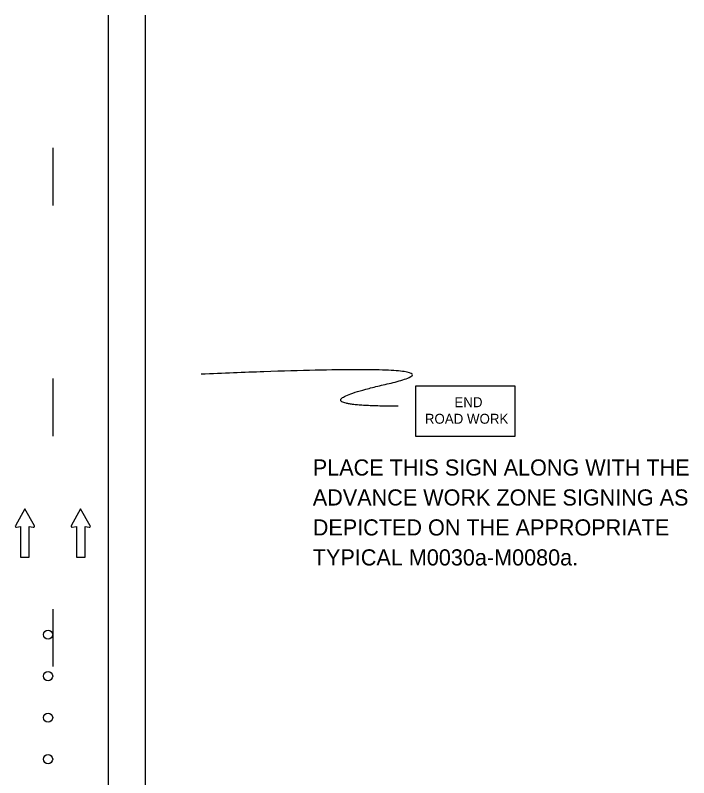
# Model space of a CAD drawing. Extents: x 16735 to 18475, y 6983 to 8262.
# Drawn here: x 17072.8 to 17364.7, y 7864.5 to 8195.2 of the extents above; entities that cross this region are included whole.
import ezdxf

# ---------------------------------------------------------------- set-up
doc = ezdxf.new("R2010")
doc.units = 0
for name, color, linetype in [('ALI_LEGAL_EX', 7, 'Continuous'), ('MT_SCRATCH_LEVEL_E', 7, 'Continuous'), ('PAVT_EDGE_EX', 7, 'Continuous'), ('TRAFFIC_SIGNS_PR', 7, 'Continuous')]:
    doc.layers.add(name, color=color, linetype=linetype)

msp = doc.modelspace()

# ---------------------------------------------------------------- linework, layer by layer
at = {"layer": 'ALI_LEGAL_EX'}
for points in [[(17089.08, 8137.7), (17089.08, 8112.7)], [(17089.08, 8037.7), (17089.08, 8012.7)], [(17089.08, 7937.7), (17089.08, 7912.7)]]:
    msp.add_lwpolyline(points, dxfattribs=at)
at = {"layer": 'MT_SCRATCH_LEVEL_E'}
for p, q in [((17077.02, 7981.08), (17072.9, 7973.84)), ((17077.02, 7981.08), (17072.9, 7973.84)), ((17081.16, 7973.84), (17077.02, 7981.08)), ((17081.16, 7973.84), (17077.02, 7981.08)), ((17101.19, 7981.08), (17097.08, 7973.84)), ((17101.19, 7981.08), (17097.08, 7973.84)), ((17105.33, 7973.84), (17101.19, 7981.08)), ((17105.33, 7973.84), (17101.19, 7981.08)), ((17073.39, 7973.15), (17075.16, 7973.47)), ((17073.39, 7973.15), (17075.16, 7973.47)), ((17075.16, 7973.47), (17075.16, 7960.21)), ((17075.16, 7973.47), (17075.16, 7960.21)), ((17078.91, 7960.21), (17078.91, 7973.47)), ((17078.91, 7973.47), (17080.68, 7973.15)), ((17078.91, 7960.21), (17078.91, 7973.47)), ((17078.91, 7973.47), (17080.68, 7973.15)), ((17097.56, 7973.15), (17099.33, 7973.47)), ((17097.56, 7973.15), (17099.33, 7973.47)), ((17099.33, 7973.47), (17099.33, 7960.21)), ((17099.33, 7973.47), (17099.33, 7960.21)), ((17103.08, 7960.21), (17103.08, 7973.47)), ((17103.08, 7973.47), (17104.85, 7973.15)), ((17103.08, 7960.21), (17103.08, 7973.47)), ((17103.08, 7973.47), (17104.85, 7973.15)), ((17075.16, 7960.21), (17078.91, 7960.21)), ((17075.16, 7960.21), (17078.91, 7960.21)), ((17099.33, 7960.21), (17103.08, 7960.21)), ((17099.33, 7960.21), (17103.08, 7960.21))]:
    msp.add_line(p, q, dxfattribs=at)
for centre, start, end in [((17073.31, 7973.61), 150.4248, 279.9638), ((17073.31, 7973.61), 150.4248, 279.9638), ((17080.75, 7973.61), 260.0362, 29.7731), ((17080.75, 7973.61), 260.0362, 29.7731), ((17097.48, 7973.61), 150.4248, 279.9638), ((17097.48, 7973.61), 150.4248, 279.9638), ((17104.92, 7973.61), 260.0362, 29.7731), ((17104.92, 7973.61), 260.0362, 29.7731)]:
    msp.add_arc(centre, 0.463, start, end, dxfattribs=at)
at = {"layer": 'PAVT_EDGE_EX'}
for p, q in [((17113.08, 8195.21), (17113.08, 7357.91)), ((17129.08, 8195.21), (17129.08, 7357.91))]:
    msp.add_line(p, q, dxfattribs=at)
at = {"layer": 'TRAFFIC_SIGNS_PR'}
msp.add_lwpolyline([(17246.28, 8012.71), (17289.48, 8012.71), (17289.48, 8034.31), (17246.28, 8034.31)], close=True, dxfattribs=at)
for centre in [(17087.06, 7926.59), (17087.06, 7908.59), (17087.06, 7890.59), (17087.06, 7872.59)]:
    msp.add_circle(centre, 2, dxfattribs=at)
msp.add_open_spline([(17238.76, 8025.64), (17191.52, 8025.64), (17276.54, 8044.98), (17153.45, 8039.49)], degree=2, dxfattribs=at)

# ---------------------------------------------------------------- texts
for s, height, p in [('END', 4.31, (17263.16, 8025.23)), ('ROAD WORK', 4.31, (17250.34, 8018.05)), ('PLACE THIS SIGN ALONG WITH THE', 7, (17201.78, 7995.58)), ('ADVANCE WORK ZONE SIGNING AS', 7, (17201.78, 7982.58)), ('DEPICTED ON THE APPROPRIATE', 7, (17201.78, 7969.58)), ('TYPICAL M0030a-M0080a.', 7, (17201.78, 7956.58))]:
    msp.add_text(s, height=height, dxfattribs=at).set_placement(p)

doc.saveas('drawing.dxf')
